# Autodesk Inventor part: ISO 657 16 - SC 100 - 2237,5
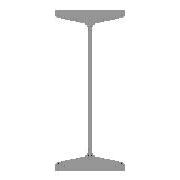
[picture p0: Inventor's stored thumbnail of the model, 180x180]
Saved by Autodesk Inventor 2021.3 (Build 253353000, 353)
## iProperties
Created: 2018-01
Part Number: ISO 657 16 - SC 100 - 2237,5
Material: Acier, doux
Description: Poutres en acier laminées à chaud - Partie 16: profilés en H (série métrique) - Cotes et propriétés de section
Document SubType Name: Modeling
Standard: ISO
Designer: Fabian Perrée
Standard Revision: First edition 1980-02-15
Standards Organization: ISO
Language: fr-FR
Size Designation: SC 100
Categories: <MemberInstance><Categories><Category DisplayName="Profilés" InternalName="089c4875-fa83-4c05-b084-43b9cc11f5ed" Mnemonic="GRDR"><CategoryParameter DisplayName=
Stock Number: SC 100
Density: 7.85 g/cm^3
Appearance: Semi-poli
Mass: 44309.5 g
Surface Area: 12051.7 cm^2
Volume: 5644.52 cm^3
_CCFamilyMember: 1
_CCFamilyDisplayName: ISO 657/16 - 1980 - Poutres en acier laminées à chaud - Partie 16: profilés en H (série métrique) - Cotes et propriétés de section
_FrameMemberDoc: Frame Member File
_Version: 25.0.0
_GetPNFromCC: 1
G_W: 100,000 mm
G_H: 100,000 mm
+A54BEF43-0FA8-4A60-B2B6-B0B0D511939D+DETAILDECOUPE1: Angle de coupe 90,00 deg
G_L: 2237,500 mm
+E90C5402-4D48-4B32-A015-53D85A7B4022+DETAILDECOUPE4: Angle de coupe 67,38 deg
IsCustomPart: 1
Author: Fabian Perrée
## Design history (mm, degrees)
node "Plan de départ"
node "Plan de fin"
sketch "Esquisse"
  geometry: L1 (-3, 0)-(-3, -26.266); L2 (-13.33, -38.149)-(-44.835, -42.577); L3 (-50, -48.518)-(-50, -50); L4 (-50, -50)-(0, -50); L5 (-26.5, -50)-(-26.5, -40); L6 (-61.333, 0)-(81.777, 0); L7 (0, 0)-(0, -50); L8 (0, -60)-(0, 80); L9 (3, 0)-(3, -26.266); L10 (13.33, -38.149)-(44.835, -42.577); L11 (50, -48.518)-(50, -50); L12 (50, -50)-(0, -50); L13 (-3, 0)-(0, 0); L14 (-3, 0)-(-3, 26.266); L15 (-13.33, 38.149)-(-44.835, 42.577); L16 (-50, 48.518)-(-50, 50); L17 (-50, 50)-(0, 50); L18 (50, 48.518)-(50, 50); L19 (13.33, 38.149)-(44.835, 42.577); L20 (3, 0)-(3, 26.266); L21 (50, 50)-(0, 50); L22 (0, 108)-(0, -88) reference; L23 (-89.955, 0)-(110.399, 0) reference; A1 r 6 centre (-44, 48.518) between (-50, 48.518) and (-44.835, 42.577); A2 r 6 centre (44, 48.518) between (44.835, 42.577) and (50, 48.518); A3 r 6 centre (44, -48.518) between (50, -48.518) and (44.835, -42.577); A4 r 6 centre (-44, -48.518) between (-44.835, -42.577) and (-50, -48.518); A5 r 12 centre (-15, 26.266) between (-3, 26.266) and (-13.33, 38.149); A6 r 12 centre (15, 26.266) between (13.33, 38.149) and (3, 26.266); A7 r 12 centre (15, -26.266) between (3, -26.266) and (13.33, -38.149); A8 r 12 centre (-15, -26.266) between (-13.33, -38.149) and (-3, -26.266); 14 further points
  constraints: 42 end point, 24 point on line, 17 symmetric about line, 16 point on circle, 16 tangent, 8 centre point, 6 equal radius, 4 collinear, 2 perpendicular, 12 other
  dimensions: "d1" = 10 vertical distance of L3.end L5.end (= G_T1); "d2" = 23.5 distance between parallel lines of L5 L3 (= -0.25 x G_T + 0.25 x G_W); "d3" = 3 distance between parallel lines of L1 L7 (= 0.5 x G_T); "d4" = 50 distance between parallel lines of L7 L3 (= 0.5 x G_W); "d9" = 50 distance from line of L1.start L4 (= 0.5 x G_H); "d14" = 98 deg angle of L2 L1 (= G_NG); "d15" = 6 radius of A1 (= G_ER); "d16" = 12 radius of A5 (= G_IR)
extrude "Corps" new body sketch "Esquisse" stored distance "d5" = 2237.5 (= G_L); taper "d6" = 0 deg
node "Driven Length"
  sketch "Sketch3"
    geometry: L1 (0, 0)-(10, 0) reference
    constraints: 2 end point, 1 horizontal
  workplane "Work Plane3"
  sketch "Sketch4"
    geometry: L1 (-2, 50)-(12, 50) reference; L2 (-2, 2287.5)-(12, 2287.5) reference
    dimensions: "d20" = 2237.5 distance between parallel lines of L1 L2 (derived)
node "Plan de construction4"
feature "Scission1"
node "Plan de construction7"
feature "Scission4"
body "Solid1"
other parameters: "G_W" = 100 (= G_H) [user parameter; used in 2 equation terms], "G_H" = 100 [user parameter; used in 2 equation terms], "G_T" = 6 [user parameter; used in 2 equation terms], "G_T1" = 10 [user parameter; used in 1 equation term], "G_L" = 2237.5 (= d20) [user parameter; used in 1 equation term], "G_ER" = 6 [user parameter; used in 1 equation term], "G_IR" = 12 [user parameter; used in 1 equation term], "G_NG" = 98 deg [user parameter; used in 1 equation term], "G_OFFSET_END" = -87.5 [user parameter; used in 1 equation term], "d18" = 2287.5 (= G_OFFSET_END + B_L), "B_L" = 2375 [user parameter; used in 1 equation term], "d19" = 90 deg
